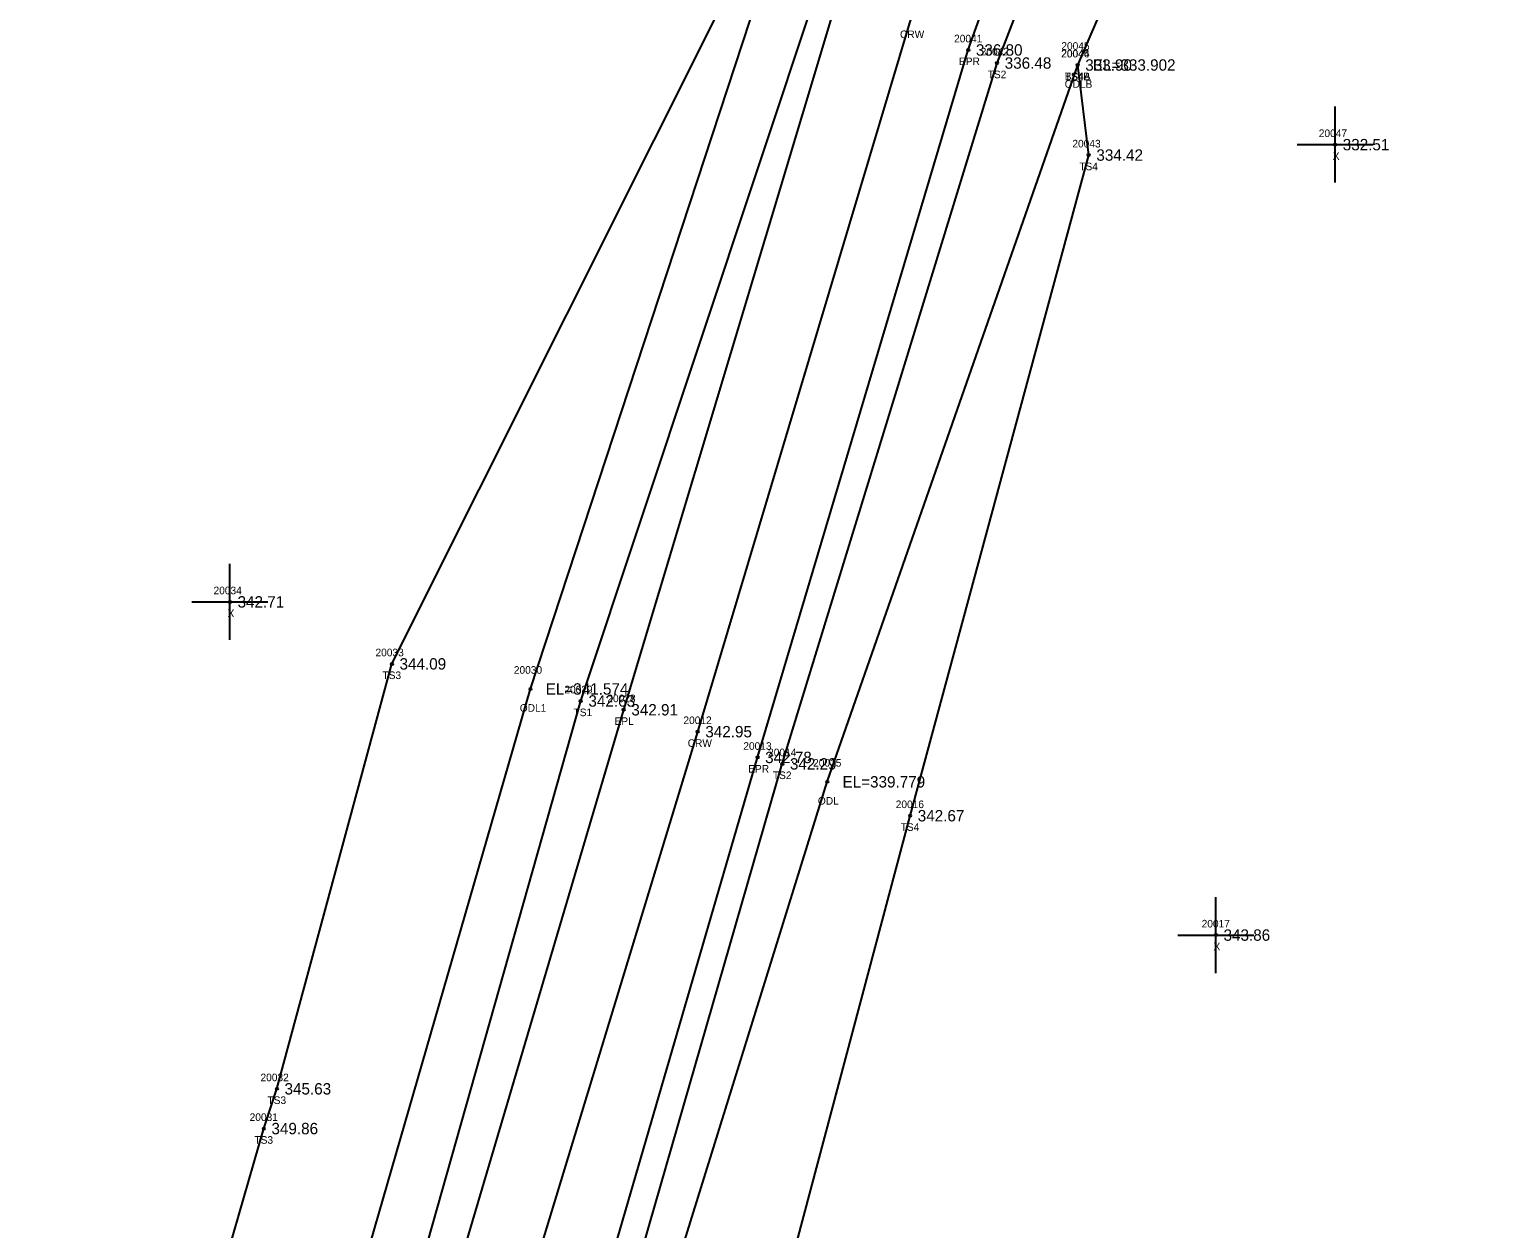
# Model space of a CAD drawing. Extents: x 2231109 to 2232328, y 1035718 to 1036919.
# Drawn here: x 2231138.4 to 2231333.2, y 1035878.7 to 1036036.4 of the extents above; entities that cross this region are included whole.
import ezdxf

# ---------------------------------------------------------------- set-up
doc = ezdxf.new("R2010")
doc.units = 0
for name, color, linetype in [('RD_DTM_BkLn1', 7, 'Continuous'), ('RD_DTM_BkLn2', 7, 'Continuous'), ('RD_DTM_BkLn_txCode', 7, 'Continuous'), ('RD_EX_H2O', 7, 'Continuous'), ('RD_EX_H2O_txCode', 7, 'Continuous'), ('RD_EX_Misc', 7, 'Continuous'), ('RD_EX_Misc_txCode', 7, 'Continuous'), ('RD_EX_Road', 7, 'Continuous'), ('RD_EX_Road_txCode', 7, 'Continuous'), ('RD_EX_TX_H2O_ELEV', 7, 'Continuous'), ('RD_EX_TX_Misc_ELEV', 7, 'Continuous'), ('RD_EX_TX_Road_ELEV', 7, 'Continuous'), ('RD_HC_Survey_ELEV', 7, 'Continuous'), ('RD_HC_Survey_txCode', 7, 'Continuous'), ('RD_SMD_Locator', 7, 'Continuous')]:
    doc.layers.add(name, color=color, linetype=linetype)

msp = doc.modelspace()

# ---------------------------------------------------------------- linework, layer by layer
at = {"layer": 'RD_DTM_BkLn1'}
msp.add_lwpolyline([(2231168.25, 1035745.18), (2231197.3, 1035848.59), (2231226.32, 1035944.04), (2231254.24, 1036037.31), (2231285.91, 1036129.66), (2231306.91, 1036176.17), (2231330.56, 1036216.58), (2231356.95, 1036257.36), (2231387.54, 1036294.26), (2231422.35, 1036330.42), (2231422.35, 1036330.4), (2231458.4, 1036362.33), (2231503.71, 1036399.67), (2231541.46, 1036424.96)], dxfattribs=at)
at = {"layer": 'RD_DTM_BkLn2'}
for points in [[(2231153.91, 1035749.54), (2231183.9, 1035852.41), (2231210.94, 1035948.08), (2231242.08, 1036041.75), (2231274.33, 1036134.79), (2231295.17, 1036181.88), (2231317.55, 1036225.12), (2231346.22, 1036265.16), (2231373.72, 1036304.6), (2231409.94, 1036342.78), (2231447.25, 1036376.56), (2231493.69, 1036413.26), (2231528.08, 1036438.61), (2231532.84, 1036438.24), (2231534.71, 1036436.33)], [(2231180.99, 1035741.83), (2231209.96, 1035844.49), (2231237.45, 1035939.8), (2231265.71, 1036032.03), (2231300.77, 1036123.1), (2231321.14, 1036169.41), (2231342.59, 1036208.04), (2231368.53, 1036247.79), (2231397.69, 1036285.75), (2231431.64, 1036319.41), (2231468.01, 1036352.78), (2231515.06, 1036385.58), (2231547.14, 1036404.2), (2231548.89, 1036408.2), (2231548.45, 1036412.54)], [(2231276.31, 1036031.77), (2231313.52, 1036118.16), (2231333.31, 1036164.6), (2231353.04, 1036201.77), (2231379.52, 1036238.63), (2231408.34, 1036274.21), (2231439.77, 1036308.83), (2231482.36, 1036339.48), (2231523.58, 1036374.84), (2231550.15, 1036393.87), (2231557.23, 1036405.65), (2231555.87, 1036413.6)], [(2231138.42, 1035755.04), (2231160.04, 1035859.88), (2231169.24, 1035891.81), (2231170.96, 1035897.04), (2231186.09, 1035952.96), (2231232.07, 1036044.88), (2231264.05, 1036138.89), (2231281.88, 1036181.64), (2231289.28, 1036185.01)], [(2231199.01, 1035737.09), (2231229.05, 1035838.1), (2231254.27, 1035932.98), (2231277.77, 1036019.92), (2231276.31, 1036031.77)]]:
    msp.add_lwpolyline(points, dxfattribs=at)
at = {"layer": 'RD_EX_H2O'}
for points in [[(2231149.43, 1035751.43), (2231176.95, 1035854.91), (2231204.32, 1035949.66), (2231235.24, 1036043.84), (2231268.21, 1036137.52), (2231289.28, 1036185.01)], [(2231185.43, 1035740.63), (2231214.2, 1035843.53), (2231243.37, 1035937.44), (2231276.31, 1036031.77)]]:
    msp.add_lwpolyline(points, dxfattribs=at)
at = {"layer": 'RD_EX_Misc'}
for p, q in [((2231310.18, 1036016.29), (2231310.18, 1036026.29)), ((2231305.18, 1036021.29), (2231315.18, 1036021.29)), ((2231164.78, 1035956.12), (2231164.78, 1035966.12)), ((2231159.78, 1035961.12), (2231169.78, 1035961.12)), ((2231294.5, 1035912.27), (2231294.5, 1035922.27)), ((2231289.5, 1035917.27), (2231299.5, 1035917.27))]:
    msp.add_line(p, q, dxfattribs=at)
at = {"layer": 'RD_EX_Road'}
for points in [[(2231158.42, 1035748.11), (2231188.37, 1035851.38), (2231216.59, 1035946.92), (2231244.77, 1036040.72), (2231278.59, 1036133.31), (2231299.55, 1036179.73), (2231323.11, 1036221.2), (2231350.7, 1036262.3), (2231381.59, 1036299.29), (2231415.97, 1036336.9), (2231452.94, 1036369.74), (2231498.19, 1036405.3), (2231537.2, 1036432.57), (2231541.46, 1036424.96)], [(2231176.43, 1035742.89), (2231206.61, 1035845.83), (2231234.19, 1035940.65), (2231261.92, 1036033.75), (2231294.68, 1036125.28), (2231316.11, 1036171.75), (2231338.19, 1036211.09), (2231363.83, 1036252.38), (2231394.08, 1036289.28), (2231427.67, 1036324.2), (2231464.37, 1036355.5), (2231508.96, 1036392.41), (2231546.55, 1036416.22), (2231541.46, 1036424.96)]]:
    msp.add_lwpolyline(points, dxfattribs=at)
at = {"layer": 'RD_SMD_Locator'}
for centre in [(2231261.92, 1036033.75), (2231265.71, 1036032.03), (2231276.31, 1036031.77), (2231276.31, 1036031.77), (2231276.31, 1036031.77), (2231310.18, 1036021.29), (2231277.77, 1036019.92), (2231164.78, 1035961.12), (2231186.09, 1035952.96), (2231204.32, 1035949.66), (2231210.94, 1035948.08), (2231216.59, 1035946.92), (2231226.32, 1035944.04), (2231234.19, 1035940.65), (2231237.45, 1035939.8), (2231243.37, 1035937.44), (2231254.27, 1035932.98), (2231294.5, 1035917.27), (2231170.96, 1035897.04), (2231169.24, 1035891.81)]:
    msp.add_circle(centre, 0.15, dxfattribs=at)

# ---------------------------------------------------------------- texts
at = {"layer": 'RD_DTM_BkLn_txCode'}
for s, p in [('20042', (2231263.55, 1036033.03)), ('20046', (2231274.13, 1036032.77)), ('20044', (2231274.16, 1036032.77)), ('TS2', (2231264.47, 1036030.03)), ('TS4B', (2231274.6, 1036029.77)), ('BS4A', (2231274.6, 1036029.77)), ('20043', (2231275.61, 1036020.92)), ('TS4', (2231276.52, 1036017.92)), ('20033', (2231183.93, 1035953.96)), ('TS3', (2231184.85, 1035950.96)), ('20029', (2231208.78, 1035949.08)), ('TS1', (2231209.98, 1035946.08)), ('20014', (2231235.58, 1035940.8)), ('TS2', (2231236.21, 1035937.8)), ('20016', (2231252.37, 1035933.98)), ('TS4', (2231253.02, 1035930.98)), ('20032', (2231168.8, 1035898.04)), ('TS3', (2231169.72, 1035895.04)), ('20031', (2231167.37, 1035892.81)), ('TS3', (2231168, 1035889.81))]:
    msp.add_text(s, height=1, dxfattribs=at).set_placement(p)
at = {"layer": 'RD_EX_H2O_txCode'}
for s, p in [('20045', (2231274.16, 1036033.77)), ('ODLB', (2231274.6, 1036028.77)), ('20030', (2231202.13, 1035951.66)), ('ODL1', (2231202.91, 1035946.66)), ('20015', (2231241.5, 1035939.44)), ('ODL', (2231242.13, 1035934.44))]:
    msp.add_text(s, height=1, dxfattribs=at).set_placement(p)
at = {"layer": 'RD_EX_Misc_txCode'}
for s, p in [('20047', (2231308.03, 1036022.29)), ('X', (2231309.87, 1036019.29)), ('20034', (2231162.62, 1035962.12)), ('X', (2231164.46, 1035959.12)), ('20017', (2231292.62, 1035918.27)), ('X', (2231294.18, 1035915.27))]:
    msp.add_text(s, height=1, dxfattribs=at).set_placement(p)
at = {"layer": 'RD_EX_Road_txCode'}
for s, p in [('20041', (2231260.05, 1036034.75)), ('EPR', (2231260.69, 1036031.75)), ('20028', (2231214.43, 1035947.92)), ('EPL', (2231215.38, 1035944.92)), ('20013', (2231232.32, 1035941.65)), ('EPR', (2231232.96, 1035938.65))]:
    msp.add_text(s, height=1, dxfattribs=at).set_placement(p)
at = {"layer": 'RD_EX_TX_H2O_ELEV'}
for s, p in [('EL=333.902', (2231278.31, 1036031.02)), ('EL=341.574', (2231206.32, 1035948.91)), ('EL=339.779', (2231245.37, 1035936.69))]:
    msp.add_text(s, height=1.5, dxfattribs=at).set_placement(p)
at = {"layer": 'RD_EX_TX_Misc_ELEV'}
for s, p in [('336.48', (2231266.71, 1036031.28)), ('333.90', (2231277.31, 1036031.02)), ('333.90', (2231277.31, 1036031.02)), ('332.51', (2231311.18, 1036020.54)), ('334.42', (2231278.77, 1036019.17)), ('342.71', (2231165.78, 1035960.37)), ('344.09', (2231187.09, 1035952.21)), ('342.63', (2231211.94, 1035947.33)), ('342.29', (2231238.45, 1035939.05)), ('342.67', (2231255.27, 1035932.23)), ('343.86', (2231295.5, 1035916.52)), ('345.63', (2231171.96, 1035896.29)), ('349.86', (2231170.24, 1035891.06))]:
    msp.add_text(s, height=1.5, dxfattribs=at).set_placement(p)
at = {"layer": 'RD_EX_TX_Road_ELEV'}
for s, p in [('336.80', (2231262.92, 1036033)), ('342.91', (2231217.59, 1035946.17)), ('342.78', (2231235.19, 1035939.9))]:
    msp.add_text(s, height=1.5, dxfattribs=at).set_placement(p)
at = {"layer": 'RD_HC_Survey_ELEV'}
msp.add_text('342.95', height=1.5, dxfattribs=at).set_placement((2231227.32, 1035943.29))
at = {"layer": 'RD_HC_Survey_txCode'}
for s, p in [('CRW', (2231252.93, 1036035.31)), ('20012', (2231224.44, 1035945.04)), ('CRW', (2231225, 1035942.04))]:
    msp.add_text(s, height=1, dxfattribs=at).set_placement(p)

doc.saveas('drawing.dxf')
